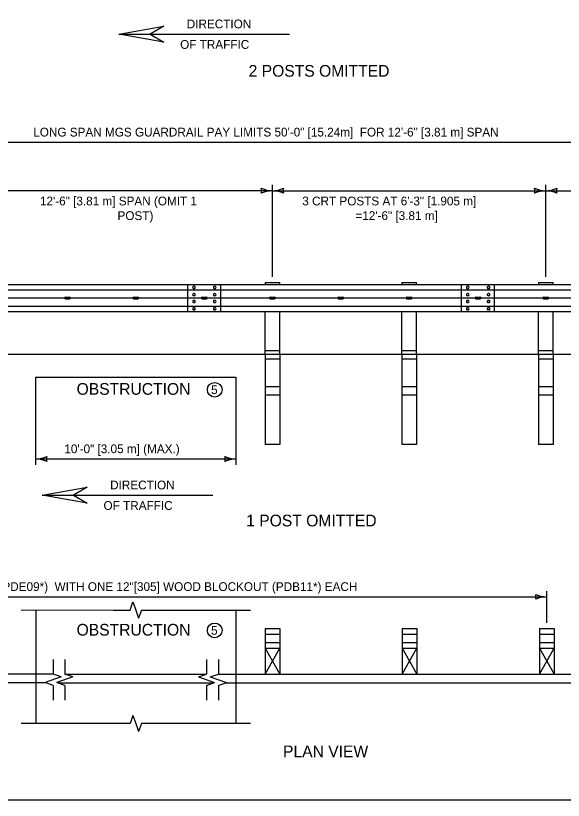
# Model space of a CAD drawing. Extents: x 49991.4 to 50021, y 49987.6 to 50011.4.
# Drawn here: x 50003.42 to 50007.16, y 49987.8 to 49993.16 of the extents above; entities that cross this region are included whole.
import ezdxf

# ---------------------------------------------------------------- set-up
doc = ezdxf.new("R2010")
doc.units = 0
for name, color, linetype in [('Level 1', 7, 'Continuous'), ('Level 2', 7, 'Continuous'), ('Level 3', 7, 'Continuous'), ('Level 4', 7, 'Continuous'), ('Level 5', 7, 'Continuous'), ('Level 6', 7, 'Continuous')]:
    doc.layers.add(name, color=color, linetype=linetype)

msp = doc.modelspace()

# ---------------------------------------------------------------- linework, layer by layer
at = {"layer": 'Level 1'}
for p, q in [((50004.1256, 49993.0337), (50005.291, 49993.0337)), ((50000.0289, 49991.3233), (50010.4985, 49991.3233)), ((50000.0289, 49991.2873), (50010.4985, 49991.2873)), ((50004.5961, 49991.138), (50004.5961, 49991.3226)), ((50004.6403, 49991.311), (50004.6367, 49991.311)), ((50004.6403, 49991.2959), (50004.6367, 49991.2959)), ((50004.7825, 49991.311), (50004.7789, 49991.311)), ((50004.7825, 49991.2959), (50004.7789, 49991.2959)), ((50005.1255, 49991.3366), (50005.1255, 49991.3233)), ((50005.1255, 49991.3366), (50005.2255, 49991.3366)), ((50005.2255, 49991.3233), (50005.2255, 49991.3366)), ((50006.06, 49991.3366), (50006.06, 49991.3233)), ((50006.06, 49991.3366), (50006.1599, 49991.3366)), ((50006.1599, 49991.3233), (50006.1599, 49991.3366)), ((50006.4686, 49991.138), (50006.4686, 49991.3226)), ((50006.5128, 49991.311), (50006.5092, 49991.311)), ((50006.5128, 49991.2959), (50006.5092, 49991.2959)), ((50006.655, 49991.311), (50006.6514, 49991.311)), ((50006.655, 49991.2959), (50006.6514, 49991.2959)), ((50006.9944, 49991.3366), (50006.9944, 49991.3233)), ((50006.9944, 49991.3366), (50007.0944, 49991.3366)), ((50007.0944, 49991.3233), (50007.0944, 49991.3366)), ((50003.7593, 49991.2373), (50003.7884, 49991.2373)), ((50004.2265, 49991.2373), (50004.2557, 49991.2373)), ((50004.6403, 49991.2611), (50004.6367, 49991.2611)), ((50004.6403, 49991.246), (50004.6367, 49991.246)), ((50004.6947, 49991.2373), (50004.7239, 49991.2373)), ((50004.7825, 49991.2611), (50004.7789, 49991.2611)), ((50004.7825, 49991.246), (50004.7789, 49991.246)), ((50005.1609, 49991.2373), (50005.1901, 49991.2373)), ((50005.6281, 49991.2373), (50005.6573, 49991.2373)), ((50006.0954, 49991.2373), (50006.1245, 49991.2373)), ((50006.5128, 49991.2611), (50006.5092, 49991.2611)), ((50006.5128, 49991.246), (50006.5092, 49991.246)), ((50006.5672, 49991.2373), (50006.5964, 49991.2373)), ((50006.655, 49991.2611), (50006.6514, 49991.2611)), ((50006.655, 49991.246), (50006.6514, 49991.246)), ((50007.0298, 49991.2373), (50007.059, 49991.2373)), ((50003.7593, 49991.2248), (50003.7884, 49991.2248)), ((50004.2265, 49991.2248), (50004.2557, 49991.2248)), ((50004.6403, 49991.2146), (50004.6367, 49991.2146)), ((50004.6403, 49991.1995), (50004.6367, 49991.1995)), ((50004.6947, 49991.2248), (50004.7239, 49991.2248)), ((50004.7825, 49991.2146), (50004.7789, 49991.2146)), ((50004.7825, 49991.1995), (50004.7789, 49991.1995)), ((50005.1609, 49991.2248), (50005.1901, 49991.2248)), ((50005.6281, 49991.2248), (50005.6573, 49991.2248)), ((50006.0954, 49991.2248), (50006.1245, 49991.2248)), ((50006.5128, 49991.2146), (50006.5092, 49991.2146)), ((50006.5128, 49991.1995), (50006.5092, 49991.1995)), ((50006.5672, 49991.2248), (50006.5964, 49991.2248)), ((50006.655, 49991.2146), (50006.6514, 49991.2146)), ((50006.655, 49991.1995), (50006.6514, 49991.1995)), ((50007.0298, 49991.2248), (50007.059, 49991.2248)), ((50000.0289, 49991.1748), (50010.4985, 49991.1748)), ((50000.0289, 49991.1388), (50010.4985, 49991.1388)), ((50004.6403, 49991.1647), (50004.6367, 49991.1647)), ((50004.6403, 49991.1496), (50004.6367, 49991.1496)), ((50004.7825, 49991.1647), (50004.7789, 49991.1647)), ((50004.7825, 49991.1496), (50004.7789, 49991.1496)), ((50005.1255, 49990.8443), (50005.1255, 49991.1388)), ((50005.2254, 49990.8443), (50005.2254, 49991.1388)), ((50006.06, 49990.8443), (50006.06, 49991.1388)), ((50006.1599, 49990.8443), (50006.1599, 49991.1388)), ((50006.5128, 49991.1647), (50006.5092, 49991.1647)), ((50006.5128, 49991.1496), (50006.5092, 49991.1496)), ((50006.655, 49991.1647), (50006.6514, 49991.1647)), ((50006.655, 49991.1496), (50006.6514, 49991.1496)), ((50006.9944, 49990.8443), (50006.9944, 49991.1388)), ((50007.0943, 49990.8443), (50007.0943, 49991.1388)), ((50010.4985, 49990.8443), (50000.0289, 49990.8443)), ((50003.5566, 49990.0907), (50003.5566, 49990.6899)), ((50003.5566, 49990.6899), (50004.9255, 49990.6899)), ((50004.9255, 49990.6899), (50004.9255, 49990.0907)), ((50003.6017, 49989.8833), (50004.7671, 49989.8833)), ((50003.5566, 49989.0992), (50003.5566, 49988.3233)), ((50004.9255, 49989.0991), (50004.9255, 49988.3233)), ((50005.1255, 49988.9722), (50005.1255, 49988.6612)), ((50005.1255, 49988.9722), (50005.2254, 49988.9722)), ((50005.2254, 49988.9722), (50005.2254, 49988.6612)), ((50006.0636, 49988.9722), (50006.0636, 49988.6612)), ((50006.0636, 49988.9722), (50006.1636, 49988.9722)), ((50006.1636, 49988.9722), (50006.1636, 49988.6612)), ((50007.0018, 49988.9722), (50007.0018, 49988.6612)), ((50007.0018, 49988.9722), (50007.1017, 49988.9722)), ((50007.1017, 49988.9722), (50007.1017, 49988.6612)), ((50005.1255, 49988.8389), (50005.2254, 49988.8389)), ((50005.1255, 49988.6612), (50005.2254, 49988.8389)), ((50005.1255, 49988.8389), (50005.2254, 49988.6612)), ((50006.0636, 49988.8389), (50006.1636, 49988.8389)), ((50006.0636, 49988.6612), (50006.1636, 49988.8389)), ((50006.0636, 49988.8389), (50006.1636, 49988.6612)), ((50007.0018, 49988.8389), (50007.1017, 49988.8389)), ((50007.0018, 49988.6612), (50007.1017, 49988.8389)), ((50007.0018, 49988.8389), (50007.1017, 49988.6612)), ((50003.6766, 49988.6612), (50000.0517, 49988.6612)), ((50003.7566, 49988.6612), (50004.7255, 49988.6612)), ((50004.8055, 49988.6612), (50010.525, 49988.6612)), ((50003.6266, 49988.6012), (50000.0015, 49988.6012)), ((50003.7066, 49988.6012), (50004.7755, 49988.6012)), ((50004.8593, 49988.6026), (50010.4711, 49988.6026))]:
    msp.add_line(p, q, dxfattribs=at)
for points in [[(49999.3835, 49998.9992), (50016.7501, 49998.9992), (50016.7501, 49987.7988), (49999.3835, 49987.7988)], [(50004.433, 49992.9795), (50004.1256, 49993.0337), (50004.433, 49993.0883), (50004.3393, 49993.0337)], [(50003.9091, 49989.8291), (50003.6017, 49989.8833), (50003.9091, 49989.9379), (50003.8154, 49989.8833)]]:
    msp.add_lwpolyline(points, close=True, dxfattribs=at)
for centre, start, end in [((50003.7593, 49991.231), 90, 180), ((50003.7884, 49991.231), 360, 90), ((50004.2265, 49991.231), 90, 180), ((50004.2557, 49991.231), 360, 90), ((50004.6947, 49991.231), 90, 180), ((50004.7239, 49991.231), 360, 90), ((50005.1609, 49991.231), 90, 180), ((50005.1901, 49991.231), 360, 90), ((50005.6281, 49991.231), 90, 180), ((50005.6573, 49991.231), 360, 90), ((50006.0954, 49991.231), 90, 180), ((50006.1245, 49991.231), 360, 90), ((50006.5672, 49991.231), 90, 180), ((50006.5964, 49991.231), 360, 90), ((50007.0298, 49991.231), 90, 180), ((50007.059, 49991.231), 360, 90), ((50003.7593, 49991.231), 180, 270), ((50003.7884, 49991.231), 270, 0), ((50004.2265, 49991.231), 180, 270), ((50004.2557, 49991.231), 270, 0), ((50004.6947, 49991.231), 180, 270), ((50004.7239, 49991.231), 270, 0), ((50005.1609, 49991.231), 180, 270), ((50005.1901, 49991.231), 270, 0), ((50005.6281, 49991.231), 180, 270), ((50005.6573, 49991.231), 270, 0), ((50006.0954, 49991.231), 180, 270), ((50006.1245, 49991.231), 270, 0), ((50006.5672, 49991.231), 180, 270), ((50006.5964, 49991.231), 270, 0), ((50007.0298, 49991.231), 180, 270), ((50007.059, 49991.231), 270, 0)]:
    msp.add_arc(centre, 0.00625, start, end, dxfattribs=at)
for centre, start_param, end_param in [((50004.6367, 49991.3035), 1.570796, 4.712389), ((50004.6403, 49991.3035), 4.712389, 7.853982), ((50004.7789, 49991.3035), 1.570796, 4.712389), ((50004.7825, 49991.3035), 4.712389, 7.853982), ((50006.5092, 49991.3035), 1.570796, 4.712389), ((50006.5128, 49991.3035), 4.712389, 7.853982), ((50006.6514, 49991.3035), 1.570796, 4.712389), ((50006.655, 49991.3035), 4.712389, 7.853982), ((50004.6367, 49991.2536), 1.570796, 4.712389), ((50004.6403, 49991.2536), 4.712389, 7.853982), ((50004.7789, 49991.2536), 1.570796, 4.712389), ((50004.7825, 49991.2536), 4.712389, 7.853982), ((50006.5092, 49991.2536), 1.570796, 4.712389), ((50006.5128, 49991.2536), 4.712389, 7.853982), ((50006.6514, 49991.2536), 1.570796, 4.712389), ((50006.655, 49991.2536), 4.712389, 7.853982), ((50004.6367, 49991.2071), 1.570796, 4.712389), ((50004.6403, 49991.2071), 4.712389, 7.853982), ((50004.7789, 49991.2071), 1.570796, 4.712389), ((50004.7825, 49991.2071), 4.712389, 7.853982), ((50006.5092, 49991.2071), 1.570796, 4.712389), ((50006.5128, 49991.2071), 4.712389, 7.853982), ((50006.6514, 49991.2071), 1.570796, 4.712389), ((50006.655, 49991.2071), 4.712389, 7.853982), ((50004.6367, 49991.1572), 1.570796, 4.712389), ((50004.6403, 49991.1572), 4.712389, 7.853982), ((50004.7789, 49991.1572), 1.570796, 4.712389), ((50004.7825, 49991.1572), 4.712389, 7.853982), ((50006.5092, 49991.1572), 1.570796, 4.712389), ((50006.5128, 49991.1572), 4.712389, 7.853982), ((50006.6514, 49991.1572), 1.570796, 4.712389), ((50006.655, 49991.1572), 4.712389, 7.853982)]:
    msp.add_ellipse(centre, major_axis=(0.00756, 0), ratio=0.998676, start_param=start_param, end_param=end_param, dxfattribs=at)
at = {"layer": 'Level 2'}
for centre in [(50004.7807, 49990.6042), (50004.7807, 49988.9601)]:
    msp.add_circle(centre, 0.05, dxfattribs=at)
at = {"layer": 'Level 3'}
for p, q in [((50008.4543, 49992.2946), (50000.0289, 49992.2946)), ((50005.1755, 49991.3766), (50005.1755, 49992.0038)), ((50007.0444, 49991.3766), (50007.0444, 49992.0038)), ((50005.1755, 49991.9638), (50003.3066, 49991.9638)), ((50005.1755, 49991.9638), (50007.0444, 49991.9638)), ((50007.0444, 49991.9638), (50010.4985, 49991.9638)), ((50004.9255, 49990.1307), (50003.5566, 49990.1307)), ((50007.0518, 49989.0122), (50007.0518, 49989.2289)), ((50001.4342, 49989.1889), (50007.0518, 49989.1889))]:
    msp.add_line(p, q, dxfattribs=at)
for centre, radius, start, end in [((50005.1847, 49992.1859), 0.2223, 247.456, 267.6395), ((50005.0473, 49991.9638), 0.0548, 342.1388, 17.8612), ((50005.187, 49991.731), 0.233, 92.8273, 112.0772), ((50005.164, 49992.1965), 0.233, 272.8273, 292.0772), ((50005.1664, 49991.7416), 0.2223, 67.456, 87.6395), ((50005.3037, 49991.9638), 0.0548, 162.1388, 197.8612), ((50007.0535, 49992.1859), 0.2223, 247.456, 267.6395), ((50006.9162, 49991.9638), 0.0548, 342.1388, 17.8612), ((50007.0559, 49991.731), 0.233, 92.8273, 112.0772), ((50007.0329, 49992.1965), 0.233, 272.8273, 292.0772), ((50007.0352, 49991.7416), 0.2223, 67.456, 87.6395), ((50007.1726, 49991.9638), 0.0548, 162.1388, 197.8612), ((50003.5451, 49990.3635), 0.233, 272.8273, 292.0772), ((50003.5474, 49989.9086), 0.2223, 67.456, 87.6395), ((50003.6848, 49990.1307), 0.0548, 162.1388, 197.8612), ((50004.9347, 49990.3529), 0.2223, 247.456, 267.6395), ((50004.7973, 49990.1307), 0.0548, 342.1388, 17.8612), ((50004.937, 49989.898), 0.233, 92.8273, 112.0772), ((50007.0609, 49989.4113), 0.2223, 247.456, 267.6395), ((50006.9235, 49989.1892), 0.0548, 342.1388, 17.8612), ((50007.0632, 49988.9565), 0.233, 92.8273, 112.0772)]:
    msp.add_arc(centre, radius, start, end, dxfattribs=at)
at = {"layer": 'Level 4'}
for p, q in [((50004.8226, 49991.138), (50004.8226, 49991.3226)), ((50006.695, 49991.138), (50006.695, 49991.3226)), ((50005.1255, 49990.8735), (50005.2254, 49990.8735)), ((50006.06, 49990.8735), (50006.1599, 49990.8735)), ((50006.9944, 49990.8735), (50007.0943, 49990.8735)), ((50005.1255, 49990.8443), (50005.1255, 49990.229)), ((50005.1255, 49990.8152), (50005.2254, 49990.8152)), ((50005.2254, 49990.8443), (50005.2254, 49990.229)), ((50006.06, 49990.8443), (50006.06, 49990.229)), ((50006.06, 49990.8152), (50006.1599, 49990.8152)), ((50006.1599, 49990.8443), (50006.1599, 49990.229)), ((50006.9944, 49990.8443), (50006.9944, 49990.229)), ((50006.9944, 49990.8152), (50007.0943, 49990.8152)), ((50007.0943, 49990.8443), (50007.0943, 49990.229)), ((50005.1255, 49990.6274), (50005.2254, 49990.6274)), ((50006.06, 49990.6274), (50006.1599, 49990.6274)), ((50006.9944, 49990.6274), (50007.0943, 49990.6274)), ((50005.1255, 49990.5691), (50005.2254, 49990.5691)), ((50006.06, 49990.5691), (50006.1599, 49990.5691)), ((50006.9944, 49990.5691), (50007.0943, 49990.5691)), ((50005.2254, 49990.229), (50005.1255, 49990.229)), ((50006.1599, 49990.229), (50006.06, 49990.229)), ((50007.0943, 49990.229), (50006.9944, 49990.229)), ((50005.1255, 49988.9347), (50005.2254, 49988.9347)), ((50006.0636, 49988.9347), (50006.1636, 49988.9347)), ((50007.0018, 49988.9347), (50007.1017, 49988.9347)), ((50005.1255, 49988.8764), (50005.2254, 49988.8764)), ((50006.0636, 49988.8764), (50006.1636, 49988.8764)), ((50007.0018, 49988.8764), (50007.1017, 49988.8764))]:
    msp.add_line(p, q, dxfattribs=at)
at = {"layer": 'Level 5'}
msp.add_line((50010.4985, 49991.231), (50000.0289, 49991.231), dxfattribs=at)
at = {"layer": 'Level 6'}
for p, q in [((50004.2021, 49989.0991), (50004.2215, 49989.154)), ((50004.2215, 49989.154), (50004.241, 49989.0991)), ((50003.4574, 49989.0992), (50004.0887, 49989.0991)), ((50004.0887, 49989.0991), (50004.2021, 49989.0991)), ((50004.241, 49989.0991), (50004.2604, 49989.0443)), ((50004.2799, 49989.0991), (50004.2604, 49989.0443)), ((50004.2799, 49989.0991), (50005.0255, 49989.0991)), ((50003.6766, 49988.7612), (50003.6766, 49988.6612)), ((50003.7566, 49988.7612), (50003.7566, 49988.6612)), ((50004.7255, 49988.7612), (50004.7255, 49988.6612)), ((50004.8055, 49988.7612), (50004.8055, 49988.6612)), ((50003.7315, 49988.6418), (50003.6766, 49988.6612)), ((50003.8115, 49988.6418), (50003.7566, 49988.6612)), ((50004.6706, 49988.6418), (50004.7255, 49988.6612)), ((50004.7506, 49988.6418), (50004.8055, 49988.6612)), ((50003.7315, 49988.6418), (50003.6218, 49988.6029)), ((50003.8115, 49988.6418), (50003.7018, 49988.6029)), ((50004.6706, 49988.6418), (50004.7803, 49988.6029)), ((50004.7506, 49988.6418), (50004.8603, 49988.6029)), ((50003.6766, 49988.5834), (50003.6218, 49988.6029)), ((50003.6766, 49988.5834), (50003.6766, 49988.4834)), ((50003.7566, 49988.5834), (50003.7018, 49988.6029)), ((50003.7566, 49988.5834), (50003.7566, 49988.4834)), ((50004.7255, 49988.5834), (50004.7803, 49988.6029)), ((50004.7255, 49988.5834), (50004.7255, 49988.4834)), ((50004.8055, 49988.5834), (50004.8603, 49988.6029)), ((50004.8055, 49988.5834), (50004.8055, 49988.4834)), ((50004.2215, 49988.3782), (50004.2021, 49988.3233)), ((50004.2215, 49988.3782), (50004.241, 49988.3233)), ((50004.2021, 49988.3233), (50003.4566, 49988.3233)), ((50004.241, 49988.3233), (50004.2604, 49988.2685)), ((50004.2799, 49988.3233), (50004.2604, 49988.2685)), ((50005.0255, 49988.3233), (50004.2799, 49988.3233))]:
    msp.add_line(p, q, dxfattribs=at)

# ---------------------------------------------------------------- texts
at = {"layer": 'Level 2'}
for s, height, p in [('DIRECTION', 0.06, (50004.5894, 49993.0737)), ('OF TRAFFIC', 0.06, (50004.5443, 49992.9337)), ('2 POSTS OMITTED', 0.08, (50005.0127, 49992.7433)), ('LONG SPAN MGS GUARDRAIL PAY LIMITS 50\'-0" [15.24m]  FOR 12\'-6" [3.81 m] SPAN', 0.06, (50003.5399, 49992.3346)), ('12\'-6" [3.81 m] SPAN (OMIT 1 ', 0.06, (50003.5856, 49991.8638)), ('3 CRT POSTS AT 6\'-3" [1.905 m]', 0.06, (50005.3795, 49991.8638)), ('POST)', 0.06, (50004.1161, 49991.7638)), (' =12\'-6" [3.81 m] ', 0.06, (50005.7204, 49991.7638)), ('OBSTRUCTION', 0.08, (50003.8362, 49990.5699)), ('5', 0.06, (50004.7558, 49990.5742)), ('10\'-0" [3.05 m] (MAX.)', 0.06, (50003.7526, 49990.1707)), ('DIRECTION', 0.06, (50004.0655, 49989.9233)), ('OF TRAFFIC', 0.06, (50004.0204, 49989.7833)), ('1 POST OMITTED', 0.08, (50004.9961, 49989.6705)), ('6 CRT POSTS (PDE09*)  WITH ONE 12"[305] WOOD BLOCKOUT (PDB11*) EACH', 0.06, (50002.7539, 49989.2289)), ('OBSTRUCTION', 0.08, (50003.8362, 49988.9243)), ('5', 0.06, (50004.7558, 49988.9301)), ('PLAN VIEW', 0.08, (50005.248, 49988.0931))]:
    msp.add_text(s, height=height, dxfattribs=at).set_placement(p)

doc.saveas('drawing.dxf')
